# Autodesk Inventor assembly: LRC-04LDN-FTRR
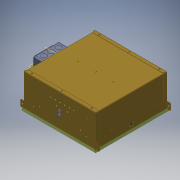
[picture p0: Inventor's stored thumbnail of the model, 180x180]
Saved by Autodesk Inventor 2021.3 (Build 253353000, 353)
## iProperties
Part Number: LRC-04LDN-FTRR
Document SubType Name: Assembly
Designer: JChurch
Author: JChurch
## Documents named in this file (4)
- X:\Revit Files\0000-Un-Zipped\COB\LRC-04LDN-FTR\LRC-04LDN-FTRR.iam
- X:\INVENTOR\830\830520-00-00.ipt
- X:\INVENTOR\881\881088-00-00.iam
- X:\INVENTOR\750\750480-FT-XX.iam
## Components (3 placed, 3 different names)
1. 830520-00-00:1 — Mate:1, Mate:2, Mate:3, Mate:4, Tangent:1, Angle:1, Insert:1
2. 881088-00-00:1 [sub-assembly] — Mate:4, Tangent:1, Angle:1
3. 750480-FT-XX:1 [sub-assembly] — Insert:1
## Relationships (7: Mate 4, Tangent 1, Angle 1, Insert 1)
- Mate:1: 830520-00-00:1
- Mate:2: 830520-00-00:1
- Mate:3: 830520-00-00:1
- Mate:4: 830520-00-00:1 ↔ 881088-00-00:1
- Tangent:1: 830520-00-00:1 ↔ 881088-00-00:1
- Angle:1: 830520-00-00:1 ↔ 881088-00-00:1
- Insert:1: 830520-00-00:1 ↔ 750480-FT-XX:1
